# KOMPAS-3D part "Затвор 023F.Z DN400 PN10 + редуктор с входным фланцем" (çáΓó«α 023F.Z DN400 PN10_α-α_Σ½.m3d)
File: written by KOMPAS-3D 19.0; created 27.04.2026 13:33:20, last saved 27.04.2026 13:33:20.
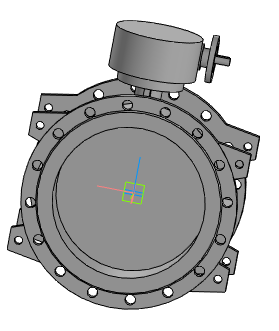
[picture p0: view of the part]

Document properties: Полное имя файла: ..\..\Затвор 023F.Z DN200-DN1600_редуктор с входным фланцем\Затвор 023F.Z DN400 PN10 + редуктор с входным фланцем.a3d

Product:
- Part/product: Затвор 023F.Z DN400 PN10 + редуктор с входным фланцем
    Масса: 185.76

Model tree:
1. Операция без истории:1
